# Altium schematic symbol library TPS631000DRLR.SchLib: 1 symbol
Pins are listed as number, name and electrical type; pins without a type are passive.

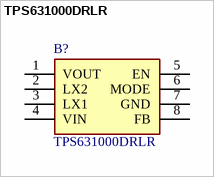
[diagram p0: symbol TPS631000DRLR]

## TPS631000DRLR
designator B?
Switching Voltage Regulators 1.5-A output current, high power density buck-boost converter; Manufacturer_Name: Texas Instruments; Geometry.Height: 0.6mm
footprint SOTFL50P160X60-8N
pins: 1 VOUT, 2 LX2, 3 LX1, 4 VIN, 5 EN, 6 MODE, 7 GND, 8 FB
